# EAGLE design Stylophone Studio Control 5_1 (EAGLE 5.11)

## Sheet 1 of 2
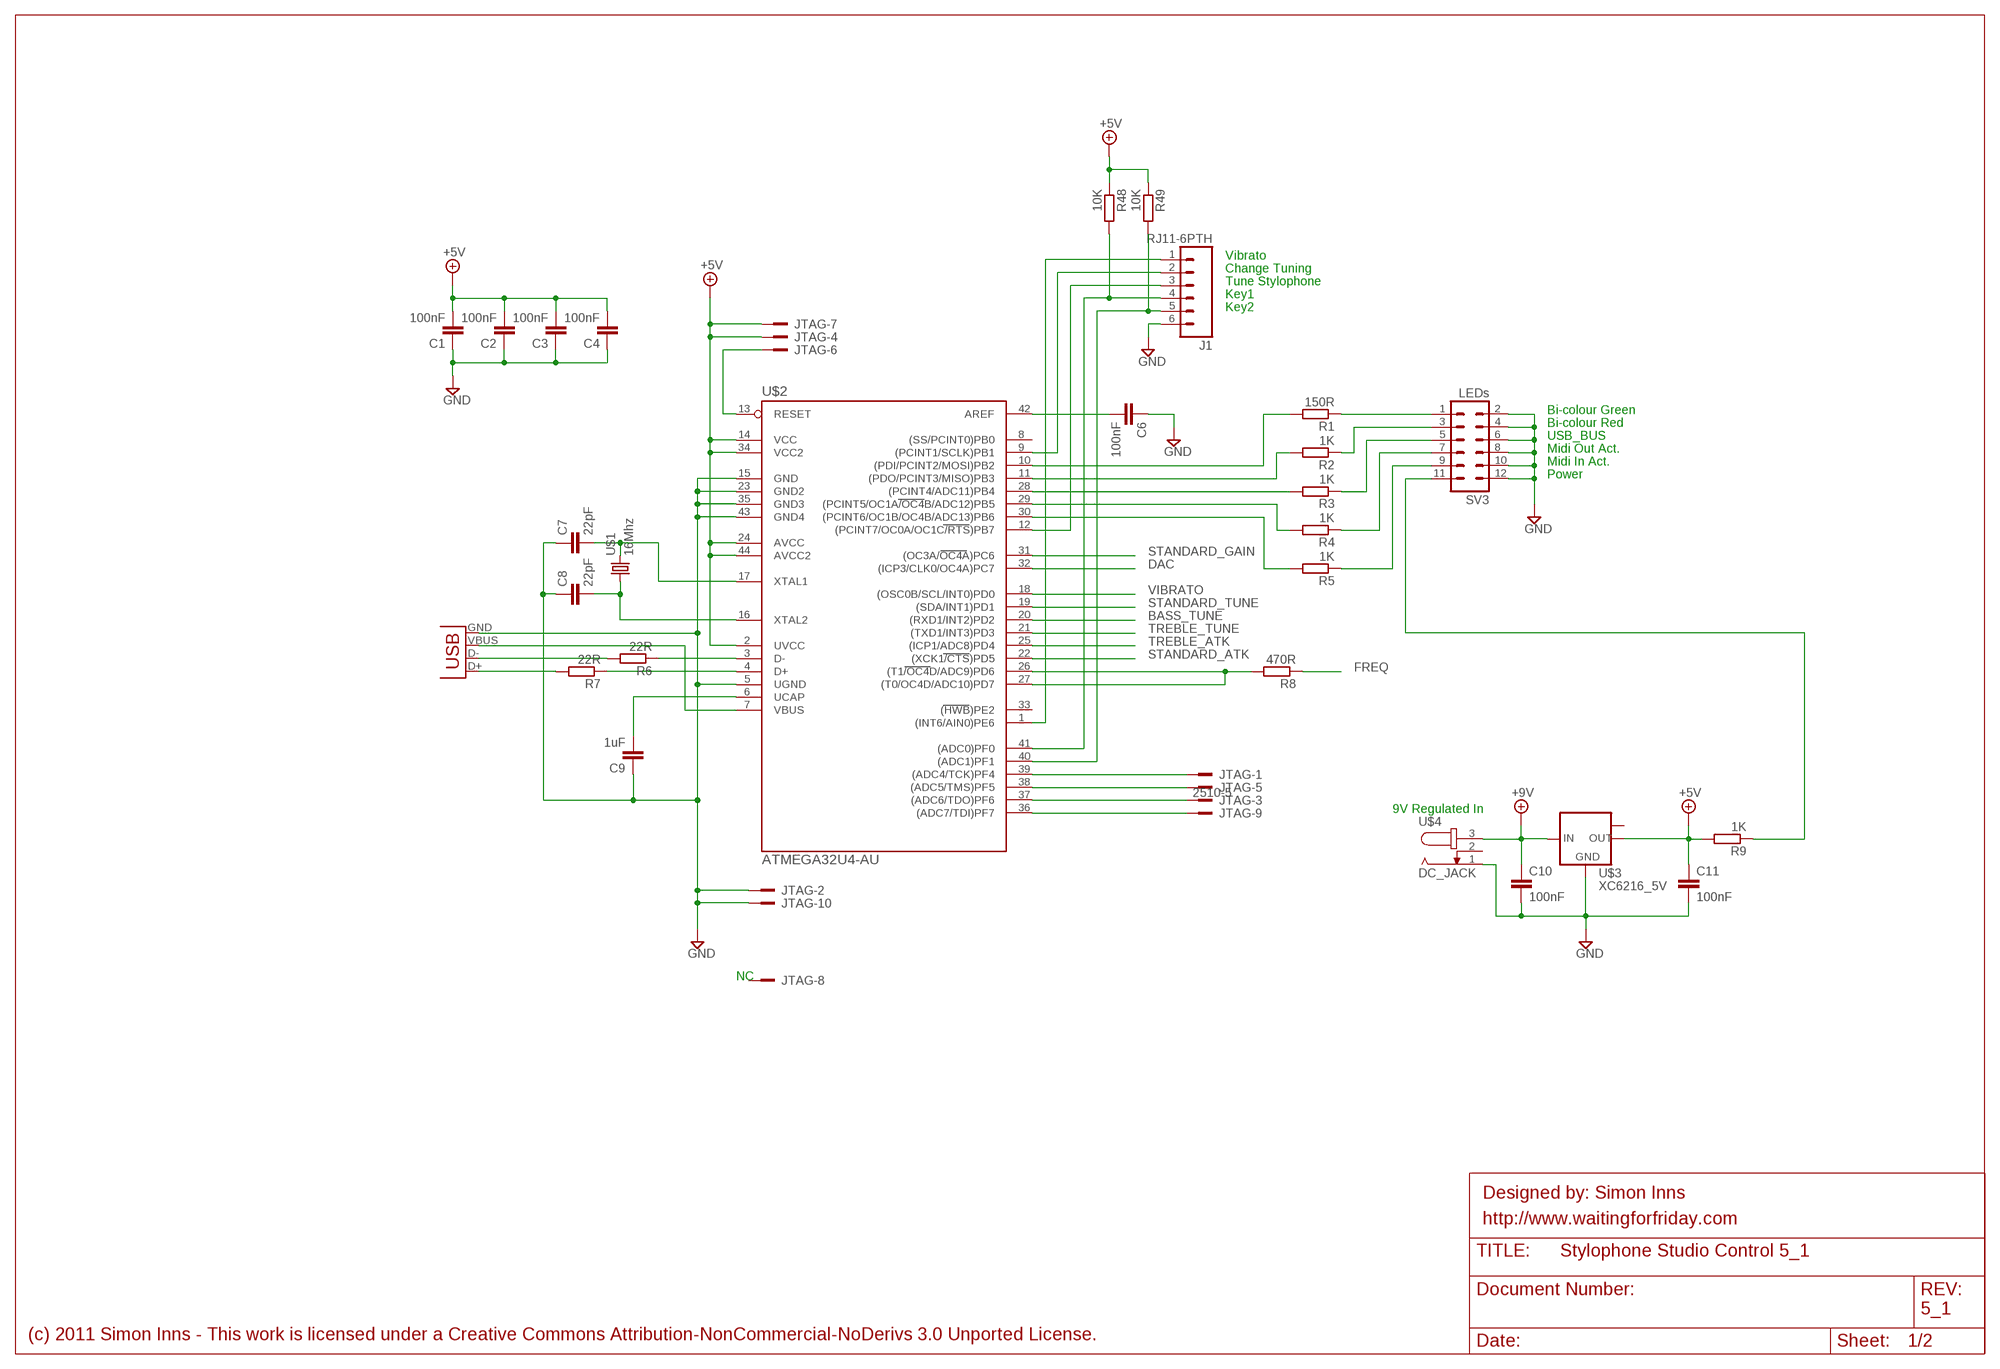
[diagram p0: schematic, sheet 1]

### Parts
C1  100nF  C-EUC0805K  [C0805K]
C2  100nF  C-EUC0805K  [C0805K]
C3  100nF  C-EUC0805K  [C0805K]
C4  100nF  C-EUC0805K  [C0805K]
C6  100nF  C-EUC0805K  [C0805K]
C7  22pF  C-EUC0805  [C0805]
C8  22pF  C-EUC0805  [C0805]
C9  1uF  C-EUC0805  [C0805]
C10  100nF  C-EUC0805K  [C0805K]
C11  100nF  C-EUC0805K  [C0805K]
J1  RJ11-6PTH  [RJ11-6]
JTAG  2510-5  [PAK100/2500-5-10]
R1  150R  R-EU_M1206  [M1206]
R2  1K  R-EU_M1206  [M1206]
R3  1K  R-EU_M1206  [M1206]
R4  1K  R-EU_M1206  [M1206]
R5  1K  R-EU_M1206  [M1206]
R6  22R  R-EU_M1206  [M1206]
R7  22R  R-EU_M1206  [M1206]
R8  470R  R-EU_M1206  [M1206]
R9  1K  R-EU_M1206  [M1206]
R48  10K  R-EU_M1206  [M1206]
R49  10K  R-EU_M1206  [M1206]
SV3  LEDs  MA06-2  [MA06-2]
U$1  16Mhz  CRYSTAL_SMD3X5MM  [CRYSTAL_SMD_3X5MM]
U$2  ATMEGA32U4-AU  [TQFP44]
U$3  XC6216_5V  [SOT223]
U$4  DC_JACK  [DC_JACK]
X1  USBPTH  [USB-B-PTH]

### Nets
+5V: C1.2 C2.2 C3.2 C4.2 C11.1 JTAG.4 JTAG.7 R9.2 R48.1 R49.1 U$2.2(UVCC) U$2.14(VCC) U$2.24(AVCC) U$2.34(VCC2) U$2.44(AVCC2) U$3.1(OUT) ; also sheet 2
+9V: C10.1 U$3.3(IN) U$4.3 ; also sheet 2
BASS_TUNE: U$2.20((RXD1/INT2)PD2) ; also sheet 2
DAC: U$2.32((ICP3/CLK0/OC4A)PC7) ; also sheet 2
FREQ: R8.1 ; also sheet 2
GND: C1.1 C2.1 C3.1 C4.1 C6.1 C7.1 C8.1 C9.1 C10.2 C11.2 J1.6 JTAG.2 JTAG.10 SV3.2 SV3.4 SV3.6 SV3.8 SV3.10 SV3.12 U$2.5(UGND) U$2.15(GND) U$2.23(GND2) U$2.35(GND3) U$2.43(GND4) U$3.2(GND) U$4.1 X1.GND ; also sheet 2
KEY1: J1.4 R48.2 U$2.41((ADC0)PF0)
KEY2: J1.5 R49.2 U$2.40((ADC1)PF1)
N$1: R8.2 U$2.26((T1/OC4D/ADC9)PD6) U$2.27((T0/OC4D/ADC10)PD7)
N$3: JTAG.6 U$2.13(RESET)
N$5: R9.1 SV3.11
N$6: R7.1 U$2.4(D+)
N$8: C8.2 U$1.1 U$2.16(XTAL2)
N$9: C7.2 U$1.2 U$2.17(XTAL1)
N$10: R3.2 U$2.28((PCINT4/ADC11)PB4)
N$12: R6.1 U$2.3(D-)
N$13: R7.2 X1.D+
N$14: R6.2 X1.D-
N$15: R4.2 U$2.29((PCINT5/OC1A/OC4B/ADC12)PB5)
N$19: U$2.7(VBUS) X1.VBUS
N$20: C9.2 U$2.6(UCAP)
N$31: R1.2 U$2.10((PDI/PCINT2/MOSI)PB2)
N$32: J1.1 U$2.1((INT6/AIN0)PE6)
N$33: R5.2 U$2.30((PCINT6/OC1B/OC4B/ADC13)PB6)
N$34: R2.2 U$2.11((PDO/PCINT3/MISO)PB3)
N$35: R1.1 SV3.1
N$36: R2.1 SV3.3
N$37: R3.1 SV3.5
N$38: R4.1 SV3.7
N$39: R5.1 SV3.9
N$41: J1.2 U$2.9((PCINT1/SCLK)PB1)
N$42: J1.3 U$2.12((PCINT7/OC0A/OC1C/RTS)PB7)
N$53: C6.2 U$2.42(AREF)
N$54: JTAG.1 U$2.39((ADC4/TCK)PF4)
N$55: JTAG.5 U$2.38((ADC5/TMS)PF5)
N$56: JTAG.3 U$2.37((ADC6/TDO)PF6)
N$57: JTAG.9 U$2.36((ADC7/TDI)PF7)
STANDARD_ATK: U$2.22((XCK1/CTS)PD5) ; also sheet 2
STANDARD_GAIN: U$2.31((OC3A/OC4A)PC6) ; also sheet 2
STANDARD_TUNE: U$2.19((SDA/INT1)PD1) ; also sheet 2
TREBLE_ATK: U$2.25((ICP1/ADC8)PD4) ; also sheet 2
TREBLE_TUNE: U$2.21((TXD1/INT3)PD3) ; also sheet 2
VIBRATO: U$2.18((OSC0B/SCL/INT0)PD0) ; also sheet 2
Unconnected: JTAG.8 U$2.8((SS/PCINT0)PB0) U$2.33((HWB)PE2) U$3.TAB(OUT1) U$4.2

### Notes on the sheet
- Vibrato
- Change Tuning
- Tune Stylophone
- Key1
- Key2
- Bi-colour Green
- Bi-colour Red
- USB_BUS
- Midi Out Act.
- Midi In Act.
- Power
- 9V Regulated In
- NC
- Designed by: Simon Inns
- http://www.waitingforfriday.com
- 5_1
- (c) 2011 Simon Inns - This work is licensed under a Creative Commons Attribution-NonCommercial-NoDerivs 3.0 Unported License.

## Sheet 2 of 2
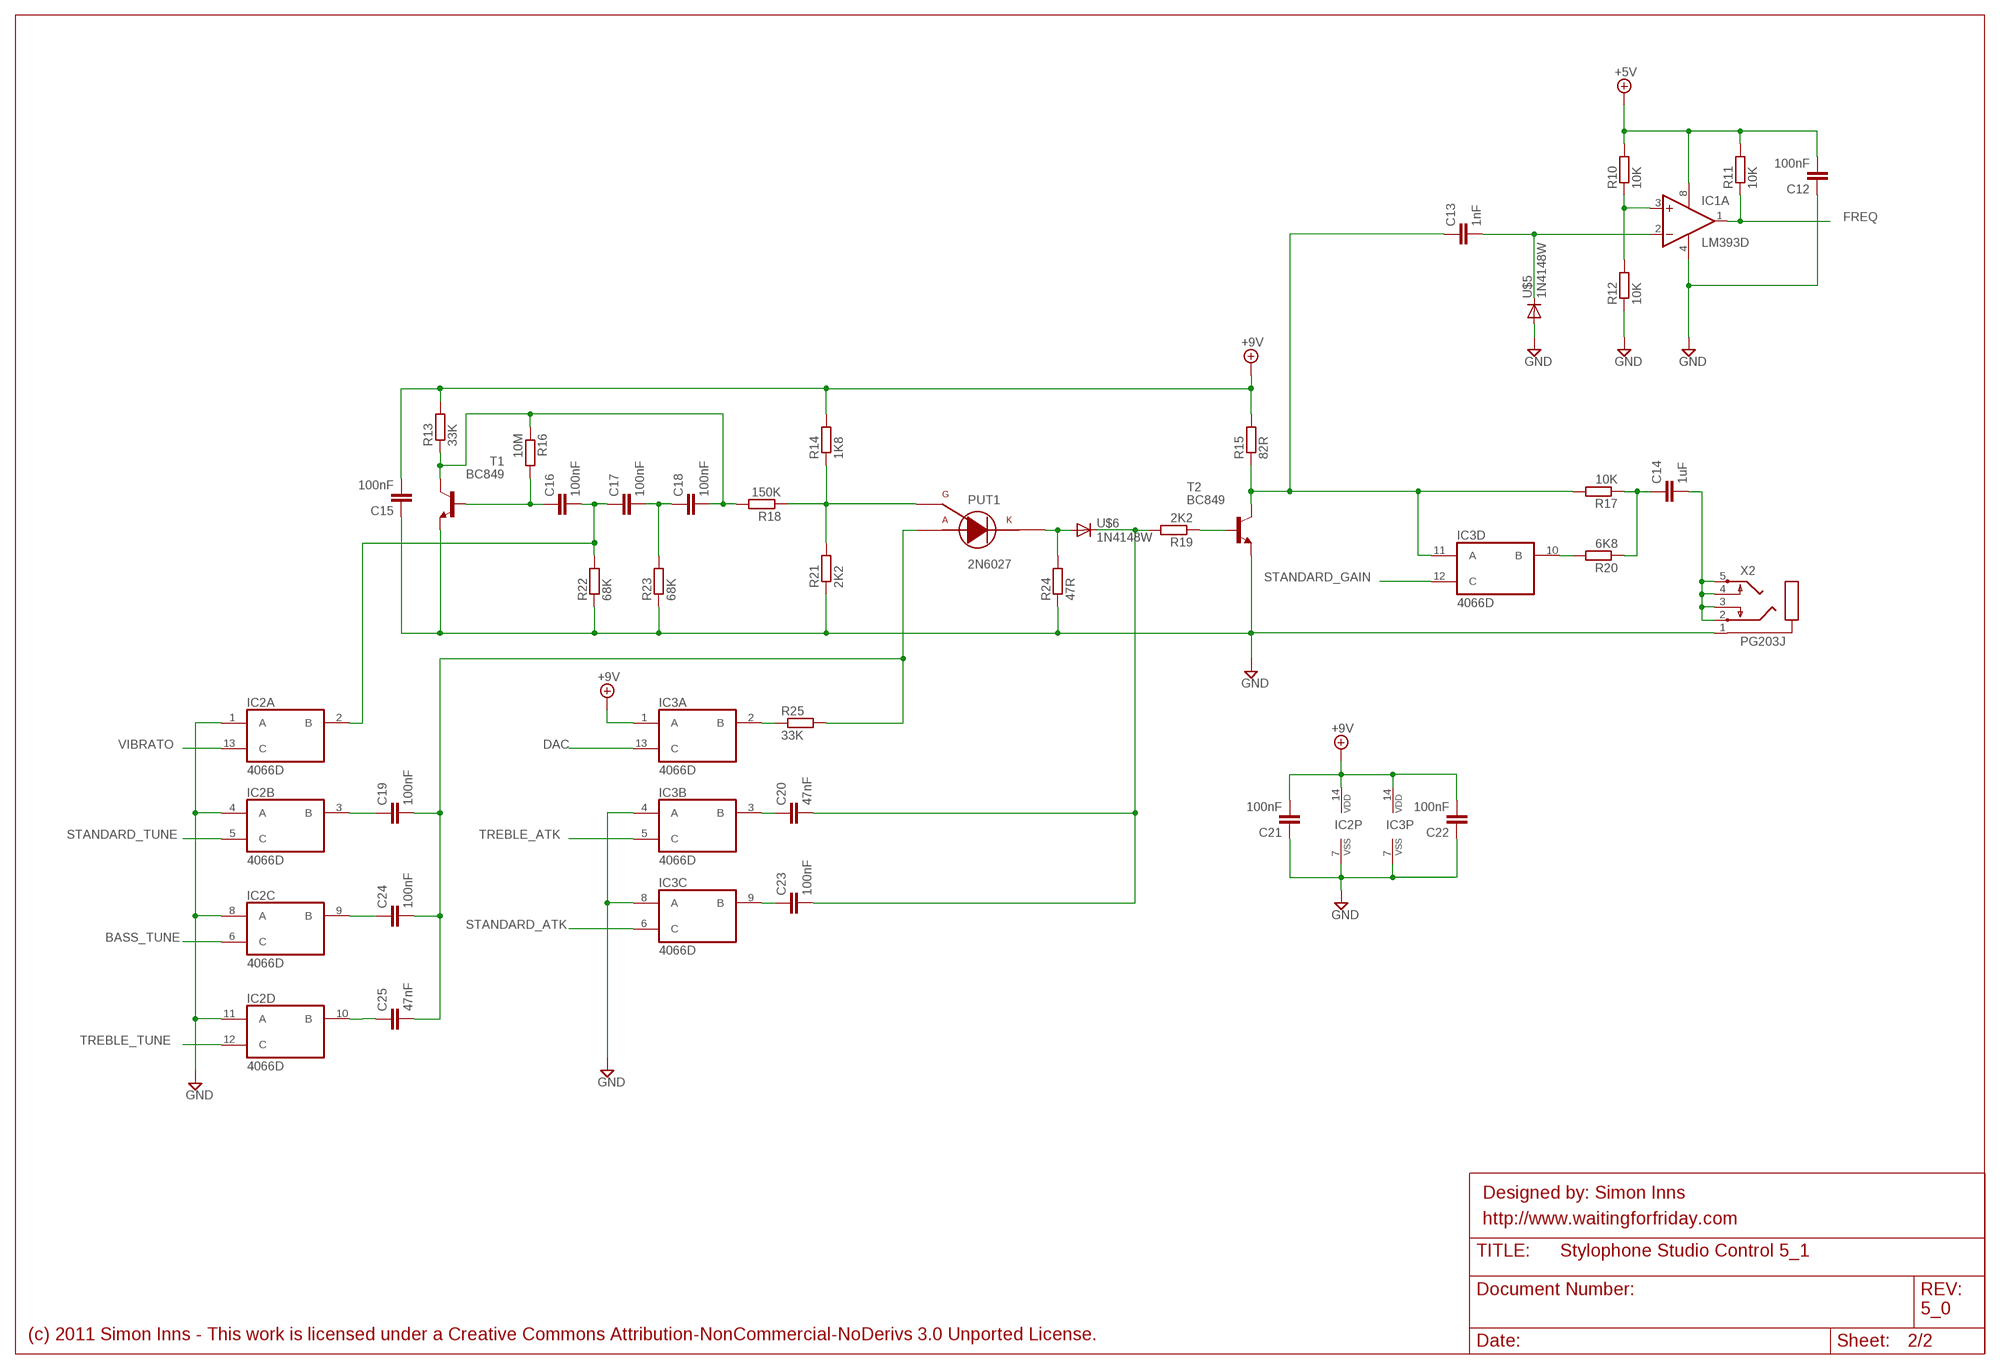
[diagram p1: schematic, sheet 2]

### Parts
C12  100nF  C-EUC0805K  [C0805K]
C13  1nF  C-EUC0805K  [C0805K]
C14  1uF  C-EUC0805K  [C0805K]
C15  100nF  C-EUC0805K  [C0805K]
C16  100nF  C-EUC0805K  [C0805K]
C17  100nF  C-EUC0805K  [C0805K]
C18  100nF  C-EUC0805K  [C0805K]
C19  100nF  C-EUC0805K  [C0805K]
C20  47nF  C-EUC0805K  [C0805K]
C21  100nF  C-EUC0805K  [C0805K]
C22  100nF  C-EUC0805K  [C0805K]
C23  100nF  C-EUC0805K  [C0805K]
C24  100nF  C-EUC0805K  [C0805K]
C25  47nF  C-EUC0805K  [C0805K]
IC1  LM393D  [SO08]
IC2  4066D  [SO14]
IC3  4066D  [SO14]
PUT1  2N6027  [TO-92]
R10  10K  R-EU_M1206  [M1206]
R11  10K  R-EU_M1206  [M1206]
R12  10K  R-EU_M1206  [M1206]
R13  33K  R-EU_M1206  [M1206]
R14  1K8  R-EU_M1206  [M1206]
R15  82R  R-EU_M1206  [M1206]
R16  10M  R-EU_M1206  [M1206]
R17  10K  R-EU_M1206  [M1206]
R18  150K  R-EU_M1206  [M1206]
R19  2K2  R-EU_M1206  [M1206]
R20  6K8  R-EU_M1206  [M1206]
R21  2K2  R-EU_M1206  [M1206]
R22  68K  R-EU_M1206  [M1206]
R23  68K  R-EU_M1206  [M1206]
R24  47R  R-EU_M1206  [M1206]
R25  33K  R-EU_M1206  [M1206]
T1  BC849  [SOT23]
T2  BC849  [SOT23]
U$5  1N4148W  [SOD123]
U$6  1N4148W  [SOD123]
X2  PG203J  [PG203J]

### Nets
+5V: C12.2 IC1.8(P:V+) R10.2 R11.2 ; also sheet 1
+9V: C15.2 C21.2 C22.2 IC2.14(P:VDD) IC3.1(A:A) IC3.14(P:VDD) R13.2 R14.2 R15.2 ; also sheet 1
BASS_TUNE: IC2.6(C:C) ; also sheet 1
CMP_V+1: C13.1 IC3.11(D:A) R15.1 R17.2 T2.3(C)
DAC: IC3.13(A:C) ; also sheet 1
FREQ: IC1.1(A:OUT) R11.1 ; also sheet 1
GND: C12.1 C15.1 C21.1 C22.1 IC1.4(P:V-) IC2.1(A:A) IC2.4(B:A) IC2.7(P:VSS) IC2.8(C:A) IC2.11(D:A) IC3.4(B:A) IC3.7(P:VSS) IC3.8(C:A) R12.1 R21.1 R22.1 R23.1 R24.1 T1.2(E) T2.2(E) U$5.A X2.1 ; also sheet 1
N$2: C13.2 IC1.2(A:-IN) U$5.C
N$4: IC1.3(A:+IN) R10.1 R12.2
N$7: C14.1 R17.1 R20.1
N$16: IC3.10(D:B) R20.2
N$58: C17.2 C18.1 R23.2
N$60: C18.2 R13.1 R16.1 R18.2 T1.3(C)
N$61: C16.1 R16.2 T1.1(B)
N$62: R19.1 T2.1(B)
N$63: PUT1.3(CATHODE) R24.2 U$6.A
N$64: C19.1 IC2.3(B:B)
N$65: C24.1 IC2.9(C:B)
N$66: C25.1 IC2.10(D:B)
N$67: PUT1.2(GATE) R14.1 R18.1 R21.2
N$68: C20.2 C23.2 R19.2 U$6.C
N$69: C14.2 X2.2 X2.3 X2.4 X2.5
N$70: IC3.2(A:B) R25.1
N$71: C19.2 C24.2 C25.2 PUT1.1(ANODE) R25.2
N$72: C16.2 C17.1 IC2.2(A:B) R22.2
N$73: C20.1 IC3.3(B:B)
N$74: C23.1 IC3.9(C:B)
STANDARD_ATK: IC3.6(C:C) ; also sheet 1
STANDARD_GAIN: IC3.12(D:C) ; also sheet 1
STANDARD_TUNE: IC2.5(B:C) ; also sheet 1
TREBLE_ATK: IC3.5(B:C) ; also sheet 1
TREBLE_TUNE: IC2.12(D:C) ; also sheet 1
VIBRATO: IC2.13(A:C) ; also sheet 1
Unconnected: IC1.5(B:+IN) IC1.6(B:-IN) IC1.7(B:OUT)

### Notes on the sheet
- Designed by: Simon Inns
- http://www.waitingforfriday.com
- 5_0
- (c) 2011 Simon Inns - This work is licensed under a Creative Commons Attribution-NonCommercial-NoDerivs 3.0 Unported License.

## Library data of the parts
C1-C4 C6-C25 = rcl:C-EU: CAPACITOR, European symbol
IC1 = linear:LM393: COMPARATOR
IC2 IC3 = 40xx:4066: Quad bilateral ANALOG SWITCH
J1 = SparkFun:RJ11-6: RJ11 Jack Simple 6 pin RJ11 jack. Commonly found on CAT3 devices and Microchip programmers. SKU: PRT-00132
JTAG = con-3m:2510-: 3M (TM) Pak 100 4-Wall Header Source: 3M; OC_FARNELL: 1788669; OC_NEWARK: unknown
PUT1 = simonslbr:2N6027: 2N6027 Programmable Unijunction Transistor in TO-92 packaging
R1-R25 R48 R49 = rcl:R-EU_: RESISTOR, European symbol
SV3 = con-lstb:MA06-2: PIN HEADER; OC_FARNELL: unknown; OC_NEWARK: unknown
T1 T2 = transistor:BC849: NPN TRANSISTOR
U$1 = simonslbr:CRYSTAL_SMD3X5MM: SMD Crystal 3.2mm X 5mm dual pads
U$2 = mega32U4:ATMEGA32U4-AU
U$3 = simonslbr:XC6216_5V: XC6216 LDO 5V Regulator
U$4 = simonslbr:DC_JACK: DC Jack with wider pads for easier soldering
U$5 U$6 = simonslbr:1N4148W: 1N4148W SOD-123 Surface mount diode
X1 = SparkFun:USB: USB Connectors USB-B-PTH is fully proven SKU : PRT-00139 USB-miniB is fully proven SKU : PRT-00587 USB-A-PCB is untested. USB-A-H is throughly reviewed, but untested. Spark Fun Electronics SKU : PRT-00437 USB-B-SMT is throughly reviewed, but untested. Needs silkscreen touching up. USB-A-S has not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
X2 = con-hirschmann:PG203J: MIC/HEADPHONE JACK KS-S stereo microphone/headphone jack PG203JN (Schukat); OC_FARNELL: unknown; OC_NEWARK: unknown

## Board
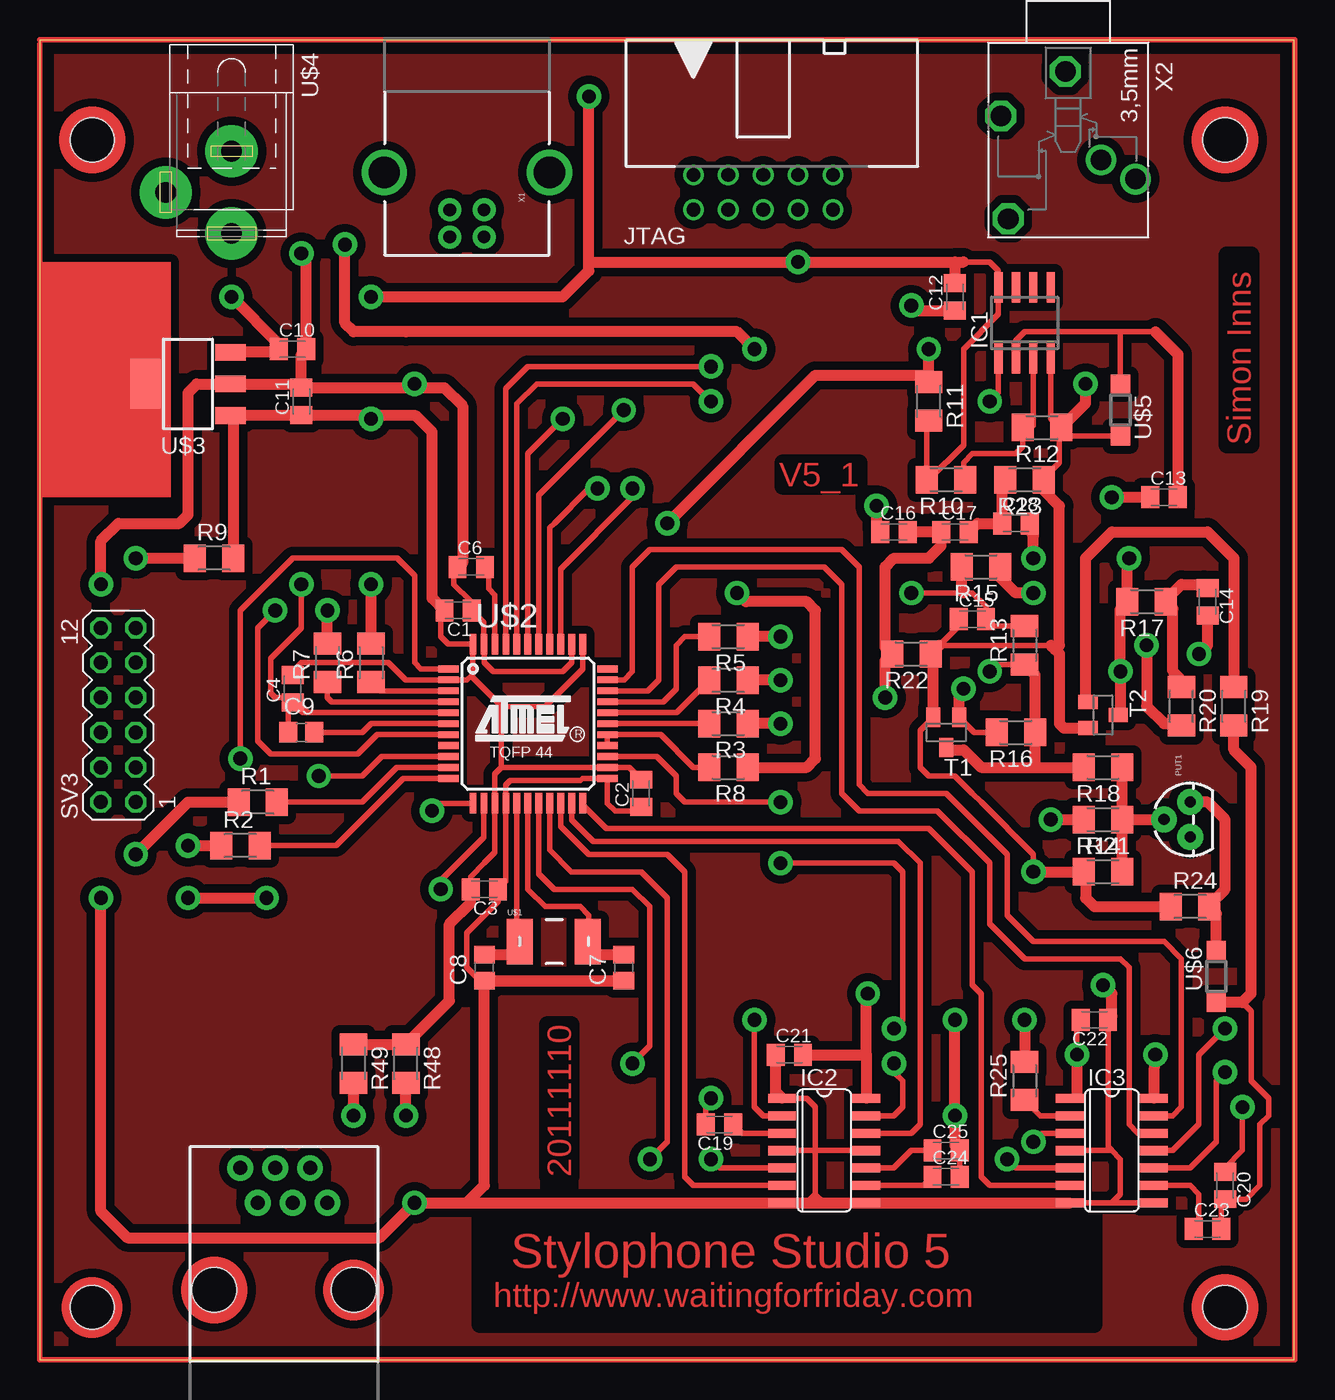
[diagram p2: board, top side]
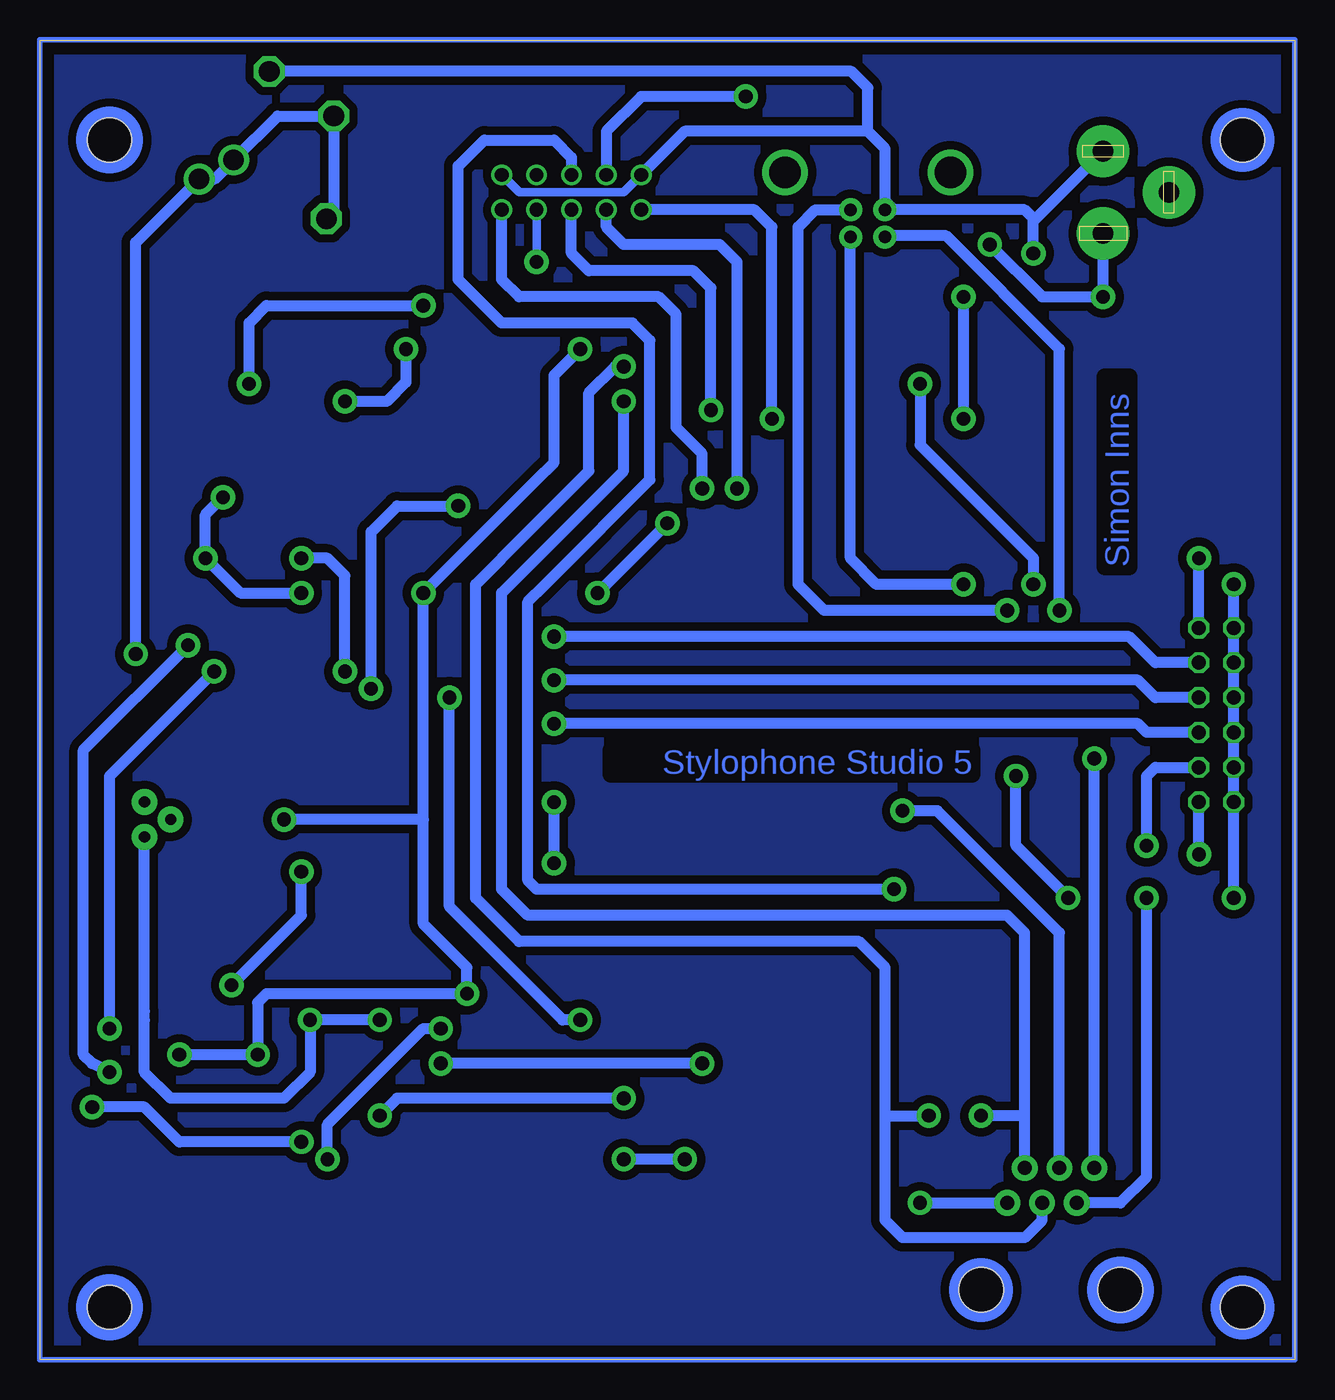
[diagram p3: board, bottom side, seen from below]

Size 91.42 x 96.19 mm. Coordinates in mm from the lower left corner, seen from the top.
Outline: 0,0 91.42,0 91.42,96.19 0,96.19 0,0
Copper layers (1*16): Top 0.035mm / dielectric 1.5mm / Bottom 0.035mm
Design rules "default": minimum track width 10mil, minimum drill 24mil, track to track 8mil, track to pad 8mil, pad to pad 8mil, via to via 8mil, smd to smd 8mil, copper to edge 40mil, drill to drill 8mil, minimum pad ring 10mil, minimum via ring 8mil, stop-mask expansion 4mil, vias tented up to drill 0mil, thermal gap 10mil
Holes 3.2 mm at 3.81,88.9 86.36,88.9 86.36,3.81 3.81,3.81
tRestrict: area 32.1,2.5 to 76.8,10.2

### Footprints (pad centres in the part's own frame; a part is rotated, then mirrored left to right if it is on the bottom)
C0805K = smd 1.3 x 1.6: 1 -1,0; 2 1,0
C0805 = smd 1.3 x 1.5: 1 -0.95,0; 2 0.95,0
SO08 = smd 0.6 x 2.2: 1 -1.905,-2.6; 2 -0.635,-2.6; 3 0.635,-2.6; 4 1.905,-2.6; 5 1.905,2.6; 6 0.635,2.6; 7 -0.635,2.6; 8 -1.905,2.6
SO14 = smd 0.66 x 2.032: 1 -3.81,-3.073; 2 -2.54,-3.073; 3 -1.27,-3.073; 4 0,-3.073; 5 1.27,-3.073; 6 2.54,-3.073; 7 3.81,-3.073; 8 3.81,3.073; 9 2.54,3.073; 10 1.27,3.073; 11 0,3.073; 12 -1.27,3.073; 13 -2.54,3.073; 14 -3.81,3.073
RJ11-6 = drill 1.016 pad 1.88 round: 1 1.905,8.89; 2 3.175,6.35; 3 4.445,8.89; 4 5.715,6.35; 5 6.985,8.89; 6 8.255,6.35 | hole 3.251: 0,0; 10.16,0
PAK100/2500-5-10 = drill 1 pad 1.422 round: 1 -5.08,-1.27; 2 -5.08,1.27; 3 -2.54,-1.27; 4 -2.54,1.27; 5 0,-1.27; 6 0,1.27; 7 2.54,-1.27; 8 2.54,1.27; 9 5.08,-1.27; 10 5.08,1.27
TO-92 = drill 0.813 pad 1.88 round: 1 -1.27,0; 2 0,1.905; 3 1.27,0
M1206 = smd 1.6 x 2: 1 -1.4,0; 2 1.4,0
MA06-2 = drill 1.016 octagon: 1 -6.35,-1.27; 2 -6.35,1.27; 3 -3.81,-1.27; 4 -3.81,1.27; 5 -1.27,-1.27; 6 -1.27,1.27; 7 1.27,-1.27; 8 1.27,1.27; 9 3.81,-1.27; 10 3.81,1.27; 11 6.35,-1.27; 12 6.35,1.27
SOT23 = smd 1 x 1.4: 1 -0.95,-1.1; 2 0.95,-1.1; 3 0,1.1
CRYSTAL_SMD_3X5MM = smd 1.9 x 3.302: 1 -2.485,-0.007; 2 2.468,-0.007
TQFP44 = smd 1.5 x 0.5: 1 -5.8,4; 2 -5.8,3.2; 3 -5.8,2.4; 4 -5.8,1.6; 5 -5.8,0.8; 6 -5.8,0; 7 -5.8,-0.8; 8 -5.8,-1.6; 9 -5.8,-2.4; 10 -5.8,-3.2; 11 -5.8,-4; 23 5.8,-4; 24 5.8,-3.2; 25 5.8,-2.4; 26 5.8,-1.6; 27 5.8,-0.8; 28 5.8,0; 29 5.8,0.8; 30 5.8,1.6; 31 5.8,2.4; 32 5.8,3.2; 33 5.8,4 | smd 0.5 x 1.5: 12 -4,-5.8; 13 -3.2,-5.8; 14 -2.4,-5.8; 15 -1.6,-5.8; 16 -0.8,-5.8; 17 0,-5.8; 18 0.8,-5.8; 19 1.6,-5.8; 20 2.4,-5.8; 21 3.2,-5.8; 22 4,-5.8; 34 4,5.8; 35 3.2,5.8; 36 2.4,5.8; 37 1.6,5.8; 38 0.8,5.8; 39 0,5.8; 40 -0.8,5.8; 41 -1.6,5.8; 42 -2.4,5.8; 43 -3.2,5.8; 44 -4,5.8
SOT223 = smd 1.219 x 2.235: 1 -2.311,-3.099; 2 0,-3.099; 3 2.311,-3.099 | smd 3.6 x 2.2: TAB 0,3.099
DC_JACK = drill 1.5 pad 3.81 round: 1 -0.46,0; 2 2.54,-4.8; 3 5.54,0
SOD123 = smd 1.4 x 1.4: A 1.9,0; C -1.9,0
USB-B-PTH = drill 0.914 pad 1.676 round: D+ 0,1.25; D- 1.981,1.25; GND 0,-1.25; VBUS 1.981,-1.25 | drill 2.286 round: S1 -2.718,-6.02; S2 -2.718,6.02
PG203J = drill 1.499 octagon: 1 -5.004,-0.203; 4 5.74,-4.369; 5 -1.753,-4.902 | drill 1.499 round: 2 2.845,4.902; 3 1.448,2.388

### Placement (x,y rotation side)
C1  30.48,54.61 180 top
C2  43.81,41.27 90 top
C3  32.38,34.29 180 top
C4  18.41,48.9 90 top
C6  31.43,57.78 0 top
C7  42.55,28.57 90 top
C8  32.38,28.57 90 top
C9  19.05,45.72 0 top
C10  18.41,73.66 0 top
C11  19.05,69.85 90 top
C12  66.67,77.47 90 top
C13  81.92,62.87 0 top
C14  85.09,55.24 270 top
C15  67.94,53.98 0 top
C16  62.23,60.33 0 top
C17  66.67,60.33 0 top
C18  71.12,60.96 0 top
C19  49.53,17.14 180 top
C20  86.36,12.7 270 top
C21  54.61,22.23 0 top
C22  76.83,24.77 180 top
C23  85.09,9.53 0 top
C24  66.04,13.34 0 top
C25  66.04,15.24 0 top
IC1  71.75,75.56 0 top
IC2  57.15,15.24 270 top
IC3  78.11,15.24 270 top
J1  12.7,5.08 0 top
JTAG  52.7,85.09 0 top
PUT1  83.82,39.37 90 top
R1  15.88,40.64 0 top
R2  14.61,37.47 0 top
R3  50.16,46.35 180 top
R4  50.16,49.53 180 top
R5  50.16,52.7 180 top
R6  24.13,50.8 90 top
R7  20.95,50.8 90 top
R8  50.16,43.18 180 top
R9  12.7,58.42 0 top
R10  66.04,64.14 180 top
R11  64.77,69.85 270 top
R12  73.03,67.94 180 top
R13  71.75,52.07 90 top
R14  77.47,39.37 180 top
R15  68.58,57.78 180 top
R16  71.12,45.72 180 top
R17  80.64,55.24 180 top
R18  77.47,43.18 180 top
R19  87,47.62 270 top
R20  83.19,47.62 270 top
R21  77.47,35.56 0 top
R22  63.5,51.44 180 top
R23  71.75,64.14 180 top
R24  83.82,33.02 0 top
R25  71.75,20.32 90 top
R48  26.67,21.59 270 top
R49  22.86,21.59 270 top
SV3  5.71,46.99 90 top
T1  66.04,45.72 180 top
T2  77.47,46.99 270 top
U$1  37.47,30.48 0 top
U$2  35.56,46.35 0 top
U$3  10.79,71.12 90 top
U$4  13.97,87.63 270 top
U$5  78.74,69.22 270 top
U$6  85.72,27.94 90 top
X1  31.11,83.82 270 top
X2  74.93,88.9 270 top

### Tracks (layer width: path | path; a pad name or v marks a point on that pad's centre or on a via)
+5V  (via drill 1 pad 1.78)
  Top 0.406: C3.2 31.39,35.2 32.38,36.2 33.16,36.97 U$2.14 33.16,42.41 33.16,42.69 33.63,43.16 | C2.2 42.94,43.16 U$2.24 33.63,43.16 | C1.2 29.21,54.34 29.21,52.7 29.76,52.16 U$2.44 31.56,49.98 31.43,49.85 | 31.43,49.85 31.11,49.53 31.09,49.55 U$2.2 29.73,49.53 26.67,49.53 25.4,50.8 19.05,50.8 18.41,50.16 C4.2 | 33.63,43.16 33.63,47.65 | 33.63,47.65 31.43,49.85 | U$2.34 39.56,50.35 36.83,47.62 33.66,47.62 33.63,47.65 | R11.2 64.64,68.32 R10.2 64.77,64.14 67.31,66.67 67.31,73.66 69.85,76.2 IC1.8 69.85,79.38 69.22,80.01 67.31,80.01
  Top 0.61: 24.13,68.81 v24.13,68.58
  Top 0.813: 19.05,68.81 U$3.1 14.1,68.6 R9.2 | 19.05,68.81 C11.1 | 19.05,68.81 24.13,68.81 27.39,68.81 28.57,67.63 28.57,55.52 C1.2 | 40.01,80.01 40.01,79.38 38.1,77.47 25.4,77.47 24.77,77.47 v24.13,77.47 | 40.01,80.01 v40.01,92.08 | 40.01,80.01 v55.24,80.01 66.67,80.01 | R49.1 R48.1 29.84,26.16 29.84,31.75 31.39,33.29 C3.2 | 66.67,80.01 67.31,80.01 | 66.67,80.01 C12.2
  Bottom 0.61: v55.24,80.01 JTAG.7
  Bottom 0.813: JTAG.4 50.16,89.53 47.62,92.08 v40.01,92.08 | v24.13,68.58 v24.13,77.47
+9V  (via drill 1 pad 1.78)
  Top 0.406: 75.56,19.15 IC3.1 | C22.2 75.56,24.5 v75.56,22.23 | R13.2 69.45,53.47 C15.2 68.94,54.88 67.94,55.88 67.31,55.88 v63.5,55.88
  Top 0.813: U$3.3 17.19,73.43 C10.1 17.41,74.03 v13.97,77.47 | IC3.14 81.18,21.06 v81.28,22.23 | v75.56,22.23 75.56,19.15 | 60.22,22.23 IC2.14 | 60.22,22.23 60.22,26.57 v60.33,26.67 | v52.07,73.66 50.8,74.93 26.67,74.93 22.86,74.93 22.23,75.56 v22.23,81.28 | C21.2 60.22,22.23 | v73.66,39.37 R14.2 | R15.2 67.18,56.01 67.31,55.88
  Bottom 0.813: U$4.3 v13.97,77.47 18.41,77.47 v22.23,81.28 | v81.28,22.23 v75.56,22.23 75.56,26.04 74.93,26.67 v60.33,26.67 60.33,28.57 63.5,31.75 63.5,39.37 | 63.5,39.37 v63.5,55.88 56.52,62.87 55.24,64.14 53.98,65.41 53.98,71.75 v52.07,73.66 | 63.5,39.37 v73.66,39.37
BASS_TUNE
  Top 0.406: U$2.20 37.96,38.88 40.01,36.83 45.72,36.83 46.99,35.56 46.99,13.34 47.62,12.7 IC2.6
CMP_V+1  (via drill 1 pad 1.78)
  Top 0.406: IC3.11 81.92,15.24 82.55,15.24 83.19,15.88 84.45,17.14 84.45,18.41 84.45,22.23 v86.36,24.13
  Top 0.813: T2.3 78.74,47.16 v78.74,50.16 78.74,54.74 R17.2 79.25,58.29 v79.38,58.42 | v78.11,62.87 C13.1 | R15.1 69.98,57.02 71.12,55.88 v72.39,55.88
  Bottom 0.813: v86.36,24.13 86.36,42.55 v78.74,50.16 | v78.11,62.87 79.38,61.59 v79.38,58.42 76.83,55.88 v72.39,55.88
DAC
  Top 0.406: U$2.32 42.57,49.55 43.18,50.16 43.18,57.78 44.45,59.05 58.42,59.05 59.69,57.78 59.69,41.91 60.33,41.27 66.04,41.27 70.48,36.83 70.48,32.38 72.39,30.48 81.92,30.48 83.19,29.21 83.19,18.41 82.55,17.78 IC3.13
FREQ  (via drill 1 pad 1.78)
  Top 0.406: IC1.1 69.85,70.48 v69.22,69.85
  Top 0.813: 64.77,71.75 R11.1 | 64.77,71.75 v64.77,73.66 | R8.1 55.88,43.18 56.52,43.81 56.52,54.61 55.88,55.24 51.44,55.24 v50.8,55.88 | v45.72,60.96 56.52,71.75 64.77,71.75
  Bottom 0.813: v69.22,69.85 66.17,69.85 R11.1 v64.77,73.66 | v50.8,55.88 v45.72,60.96
GND  (via drill 1 pad 1.78)
  Top 0.406: C2.1 43.55,40.01 41.91,40.01 41.36,40.55 U$2.23 39.56,42.35 39.37,42.23 34.29,42.23 33.96,41.9 U$2.15 33.96,34.87 C3.1 33.38,33.38 31.11,31.11 31.11,28.57 31.75,27.94 32.07,27.94 C8.1 | U$2.35 38.76,50.83 38.1,50.16 33.02,50.16 32.38,50.8 32.38,52.13 U$2.43 32.36,53.73 C1.1 31.39,54.7 31.39,55.29 30.16,56.52 30.16,57.52 C6.1 | 17.78,46.04 C9.1 18.1,47.58 C4.1 19.16,47.16 U$2.5 19.52,47.16 18.41,48.26 17.14,48.26 16.83,48.58 16.83,51.12 19.05,53.34 v19.05,56.52 | 55.88,11.43 IC2.7 55.88,11.43 | IC2.8 57.15,11.43 56.52,12.06 | 55.88,11.43 56.52,12.06 | 56.52,12.06 56.52,15.24 | 56.52,15.24 56.52,18.41 55.88,19.05 IC2.1 | 56.52,15.24 IC2.4 | 56.52,15.24 IC2.11 | IC3.8 IC3.7 78.11,11.43 78.74,12.06 78.74,14.61 78.11,15.24 | 78.11,15.24 IC3.4 78.11,15.24 | 56.52,15.24 IC2.11 | 56.52,12.06 56.52,15.24 | 55.88,11.43 56.52,12.06 | 56.52,15.24 IC2.11 | 56.52,12.06 56.52,15.24 | 78.11,15.24 77.83,15.51 C22.1 | 65.53,52.07 73.66,52.07 | v72.39,35.56 72.39,36.83 68.58,40.64 67.94,41.27 66.67,42.55 64.77,42.55 64.14,43.18 64.14,45.87 T1.2 | C15.1 66.94,53.48 R22.1 | R23.1 73.16,64.27 74.3,65.41 74.3,67.18 R12.1 | R12.1 74.42,67.81 73.66,68.58 IC1.4 | U$5.A 74.43,67.31 R12.1
  Top 0.813: C11.2 19.05,71.12 U$3.2 11.43,71.12 10.79,70.48 10.79,61.59 10.16,60.96 5.71,60.96 4.45,59.69 v4.45,56.52 | C11.2 19.05,73.3 C10.2 19.41,80.28 v19.05,80.64 | C11.2 27.3,70.85 | 27.3,70.85 29.48,70.85 30.8,69.53 30.8,58.05 C6.1 | v4.45,33.66 4.45,10.79 6.35,8.89 24.77,8.89 v27.3,11.43 31.11,11.43 | 27.3,70.85 v27.3,71.12 | C8.1 C7.1 32.7,27.62 32.38,27.3 32.38,12.7 31.11,11.43 | 31.11,11.43 55.88,11.43 57.15,11.43 IC3.7 | IC2.1 53.61,19.52 C21.1 | R21.1 v72.39,35.56 R21.1 | v77.47,27.3 78.11,26.67 78.11,25.04 C22.1 | R24.1 76.83,33.02 76.2,33.66 76.2,35.43 R21.1 | T2.2 74.61,46.04 74.3,46.35 74.3,51.44 73.98,51.75 | 73.66,52.07 73.98,51.75 | 65.53,52.07 R22.1 65.09,51.24 T1.2 | R23.1 73.16,63.37 74.3,62.23 74.3,52.07 73.98,51.75 | C12.1 63.87,76.47 v63.5,76.83 | v76.2,71.12 76.2,69.72 R12.1
  Bottom 0.61: JTAG.2 48.9,85.09 56.52,85.09 JTAG.10
  Bottom 0.813: v19.05,80.64 19.05,83.01 18.96,83.1 | 18.96,83.1 U$4.1 | 29.21,83.82 19.68,83.82 18.96,83.1 | 29.21,83.82 X1.GND | SV3.6 SV3.4 SV3.2 v4.45,33.66 | SV3.6 SV3.8 SV3.10 SV3.12 | SV3.6 v4.45,56.52 | JTAG.2 44.45,89.53 31.11,89.53 | 30.8,89.22 29.84,88.27 29.84,84.45 29.21,83.82 | 30.8,89.22 31.11,89.53 | X2.1 32.31,93.9 31.11,92.71 31.11,89.53 | 30.8,89.22 31.11,89.53 | v27.3,11.43 J1.6 | v19.05,56.52 19.05,58.42 27.3,66.67 v27.3,71.12 | v72.39,35.56 72.39,32.38 v77.47,27.3 | v63.5,76.83 74.93,76.83 76.2,75.56 v76.2,71.12
KEY1  (via drill 1 pad 1.78)
  Top 0.406: U$2.41 33.96,70.79 35.56,72.39 v48.9,72.39
  Top 0.813: v26.67,17.78 R48.2
  Bottom 0.813: v48.9,72.39 49.53,72.39 51.44,70.48 51.44,64.77 52.7,63.5 55.88,60.33 59.69,56.52 59.69,33.66 56.52,30.48 31.75,30.48 29.84,28.57 29.84,17.78 | 29.84,17.78 29.84,10.16 28.57,8.89 19.68,8.89 18.41,10.16 J1.4 | 29.84,17.78 v26.67,17.78
KEY2  (via drill 1 pad 1.78)
  Top 0.406: U$2.40 34.76,69.69 36.2,71.12 47.62,71.12 v48.9,69.85
  Top 0.813: v22.86,17.78 R49.2
  Bottom 0.813: v48.9,69.85 48.9,64.77 52.07,61.59 55.24,58.42 57.78,55.88 57.78,34.29 55.88,32.38 20.95,32.38 19.68,31.11 19.68,17.78 | J1.5 19.68,17.78 | 19.68,17.78 v22.86,17.78
N$1
  Top 0.406: U$2.26 U$2.27 45.25,45.55 47.62,43.18 R8.2
N$2
  Top 0.406: 78.74,74.93 71.75,74.93 71.12,74.3 IC1.2 | 78.74,74.93 81.28,74.93 | 78.74,74.93 U$5.C
  Top 0.813: C13.2 82.92,73.3 81.28,74.93
N$3  (via drill 1 pad 1.78)
  Top 0.406: v29.21,34.29 29.21,34.92 31.75,37.47 32.36,38.08 U$2.13
  Bottom 0.813: JTAG.6 52.7,87.63 53.98,88.9 59.05,88.9 60.96,87 60.96,78.74 57.78,75.56 48.26,75.56 46.99,74.3 46.99,64.14 53.98,57.15 54.61,56.52 55.88,55.24 55.88,34.92 55.24,34.29 v29.21,34.29
N$4
  Top 0.406: R10.1 67.31,64.27 67.31,65.41 67.94,66.04 71.12,66.04 71.62,66.55 R12.2 | R12.2 71.75,67.31 | IC1.3 72.39,68.08 R12.2
  Top 0.813: R10.1 67.31,64.27
N$5  (via drill 1 pad 1.78)
  Top 0.813: v6.99,58.42 R9.1
  Bottom 0.813: SV3.11 v6.99,58.42
N$6
  Top 0.406: U$2.4 21.26,47.95 20.95,48.26 R7.1
N$7
  Top 0.813: C14.1 84.82,56.52 83.19,56.52 82.05,55.38 R17.1 82.55,54.74 82.55,50.16 83.19,49.53 R20.1
N$8
  Top 0.406: U$2.16 34.76,30.69 U$1.1 34.04,29.53
  Top 0.813: C8.2 34.6,29.52 34.92,29.84 34.92,30.42 U$1.1
N$9
  Top 0.406: U$2.17 35.56,34.29 36.83,33.02 39.37,33.02 40.01,32.38 40.01,30.55 U$1.2
  Top 0.813: C7.2 40.32,29.52 40.01,29.21 40.01,30.4 U$1.2
N$10
  Top 0.406: U$2.28 R3.2
N$11
  pour Top (isolate 0.61): 0,95.89 91.44,95.89 91.44,0 0,0
N$12
  Top 0.406: U$2.3 24.77,48.76 R6.1
N$13  (via drill 1 pad 1.78)
  Top 0.813: R7.2 v20.95,54.61
  Bottom 0.813: v20.95,54.61 34.29,54.61 36.2,56.52 36.2,82.55 34.92,83.82 X1.D+
N$14  (via drill 1 pad 1.78)
  Top 0.813: R6.2 v24.13,56.52
  Bottom 0.813: v24.13,56.52 30.48,56.52 32.38,58.42 32.38,81.82 X1.D-
N$15
  Top 0.406: U$2.29 46.39,47.16 R4.2
N$16  (via drill 1 pad 1.78)
  Top 0.406: IC3.10 83.82,13.97 85.72,15.88 85.72,20.32 v86.36,20.95
  Top 0.813: v80.64,52.07 80.64,47.62 81.92,46.35 83.06,46.35 R20.2
  Bottom 0.813: v86.36,20.95 87.63,21.59 88.27,22.23 88.27,44.45 v80.64,52.07
N$17
  pour Bottom (isolate 0.61): 0,95.89 91.44,95.89 91.44,0 0,0
N$18
  Top 0.406: 0,96.2 91.44,96.2 91.44,0 0,0 0,95.89
N$19  (via drill 1 pad 1.78)
  Top 0.406: U$2.7 24.6,45.55 23.18,44.13 16.83,44.13 15.88,45.09 15.88,53.34 v17.14,54.61
  Bottom 0.813: v17.14,54.61 17.14,73.66 25.4,81.92 29.79,81.92 X1.VBUS
N$20
  Top 0.406: U$2.6 24.13,46.35 23.5,45.72 C9.2
N$21
  Bottom 0.406: 0,96.2 91.44,96.2 91.44,0 0,0 0,96.2
N$31
  Top 0.406: U$2.10 26.01,43.16 23.5,40.64 R1.2
N$32  (via drill 1 pad 1.78)
  Top 0.406: U$2.1 27.75,50.35 27.3,50.8 27.3,57.15 26.04,58.42 18.41,58.42 14.61,54.61 v14.61,43.81
  Bottom 0.813: J1.1 v14.61,43.81
N$33
  Top 0.406: U$2.30 45.28,47.95 45.41,47.95 46.35,48.9 46.35,52.07 46.99,52.7 R5.2
N$34
  Top 0.406: U$2.11 26.48,42.35 21.59,37.47 R2.2
N$35  (via drill 1 pad 1.78)
  Top 0.813: R1.1 10.79,40.64 v6.99,36.83
  Bottom 0.813: v6.99,36.83 SV3.1
N$36  (via drill 1 pad 1.78)
  Top 0.813: v10.79,37.47 R2.1
  Bottom 0.813: v10.79,37.47 10.79,42.55 10.16,43.18 SV3.3
N$37  (via drill 1 pad 1.78)
  Top 0.813: v53.98,46.35 R3.1
  Bottom 0.813: v53.98,46.35 11.43,46.35 10.79,45.72 SV3.5
N$38  (via drill 1 pad 1.78)
  Top 0.813: v53.98,49.53 R4.1
  Bottom 0.813: v53.98,49.53 11.43,49.53 10.16,48.26 SV3.7
N$39  (via drill 1 pad 1.78)
  Top 0.813: v53.98,52.7 R5.1
  Bottom 0.813: v53.98,52.7 12.06,52.7 10.16,50.8 SV3.9
N$41  (via drill 1 pad 1.78)
  Top 0.406: U$2.9 24.91,43.95 23.5,42.55 v20.32,42.55
  Top 0.813: v10.79,33.66 v16.51,33.66
  Bottom 0.813: v20.32,42.55 20.32,37.47 v16.51,33.66 | v10.79,33.66 10.79,13.34 12.7,11.43 J1.2
N$42  (via drill 1 pad 1.78)
  Top 0.406: v28.57,40.01 29.12,40.55 U$2.12
  Bottom 0.813: J1.3 17.14,31.11 26.04,40.01 v28.57,40.01
N$53
  Top 0.406: U$2.42 33.16,55.74 32.7,56.2 32.7,57.52 C6.2
N$54  (via drill 1 pad 1.78)
  Top 0.406: U$2.39 35.56,66.04 v38.1,68.58
  Bottom 0.813: v38.1,68.58 38.1,82.55 39.37,83.82 JTAG.1
N$55  (via drill 1 pad 1.78)
  Top 0.406: U$2.38 36.36,63.03 v42.55,69.22
  Bottom 0.813: v42.55,69.22 42.55,78.11 43.81,79.38 51.44,79.38 52.7,80.64 JTAG.5
N$56  (via drill 1 pad 1.78)
  Top 0.406: v40.64,63.5 40.01,63.5 37.47,60.96 37.16,60.66 U$2.37
  Bottom 0.813: JTAG.3 50.16,82.55 48.9,81.28 41.91,81.28 40.64,80.01 v40.64,63.5
N$57  (via drill 1 pad 1.78)
  Top 0.406: U$2.36 37.96,57.65 43.18,62.87 v43.18,63.5
  Bottom 0.813: v43.18,63.5 43.18,66.04 45.09,67.94 45.09,76.2 46.35,77.47 56.52,77.47 57.78,78.74 JTAG.9
N$58
  Top 0.813: R23.2 70.12,63.9 C18.1 68.31,60.96 C17.2
N$60  (via drill 1 pad 1.78)
  Top 0.406: R13.1 69.72,50.67 v69.22,50.16
  Top 0.813: 72.39,43.18 R18.2 | R13.1 72.52,49.91 R16.1 72.52,43.31 72.39,43.18 | 72.39,43.18 68.58,43.18 67.31,44.45 66.21,44.45 T1.3 | v72.39,58.42 72.39,60.05 C18.2
  Bottom 0.813: v72.39,58.42 70.48,58.42 69.22,57.15 v69.22,50.16
N$61  (via drill 1 pad 1.78)
  Top 0.406: R16.2 68.09,45.72 T1.1
  Top 0.813: T1.1 66.99,48.58 v67.31,48.9 | v60.96,62.23 60.96,60.59 C16.1
  Bottom 0.813: v67.31,48.9 67.31,60.33 65.41,62.23 v60.96,62.23
N$62
  Top 0.813: R19.1 87,58.42 85.09,60.33 78.11,60.33 76.2,58.42 76.2,48.11 T2.1
N$63
  Top 0.813: PUT1.3 85.09,40.64 86.36,39.37 86.36,34.29 85.22,33.15 R24.2 85.72,32.52 U$6.A
N$64
  Top 0.406: IC2.3 51.16,16.51 C19.1
N$65
  Top 0.406: IC2.9 64.41,12.7 C24.1
N$66
  Top 0.406: IC2.10 62.23,13.97 63.5,15.24 C25.1
N$67
  Top 0.813: R21.2 R14.1 | R14.1 PUT1.2 | R14.1 R18.1
N$68
  Top 0.406: C23.2 86.09,11.43 C20.2 87.9,11.7 88.9,12.7 88.9,17.14 89.53,17.78 89.53,19.05 88.27,20.32 88.27,25.4 87.62,26.04
  Top 0.813: U$6.C 87.62,26.04 88.27,26.68 88.27,43.18 87,44.45 R19.2
N$69  (via drill 1 pad 1.78)
  Top 0.813: C14.2 85.09,52.07 v84.45,51.44
  Bottom 0.813: X2.4 70.03,83.69 X2.5 74.12,90.65 X2.3 78.72,86.06 X2.2 84.45,81.43 v84.45,51.44
N$70
  Top 0.406: IC3.2 72.89,17.78 R25.1
N$71  (via drill 1 pad 1.78)
  Top 0.406: C25.2 C24.2 | C19.2 48.53,18.78 v48.9,19.05
  Top 0.813: C25.2 66.67,15.61 v66.67,17.78 v66.67,24.77 | v71.75,24.77 R25.2
  Bottom 0.813: v48.9,19.05 65.41,19.05 v66.67,17.78 | v66.67,24.77 v71.75,24.77 71.75,20.95 73.66,19.05 81.92,19.05 83.82,20.95 83.82,24.77 83.82,25.4 PUT1.1
N$72  (via drill 1 pad 1.78)
  Top 0.406: IC2.2 52.7,17.78 52.07,18.41 v52.07,24.77
  Top 0.813: v61.59,48.26 61.59,50.93 R22.2 61.59,51.94 61.59,57.78 62.23,58.42 64.77,58.42 65.67,59.33 C17.1 C16.2
  Bottom 0.813: v52.07,24.77 53.34,24.77 61.59,33.02 v61.59,48.26
N$73  (via drill 1 pad 1.78)
  Top 0.406: v72.39,15.88 73.03,16.51 IC3.3 | C20.1 86.36,13.97 87.63,15.24 v87.63,18.41
  Bottom 0.813: v87.63,18.41 83.82,18.41 81.28,15.88 v72.39,15.88
N$74
  Top 0.406: IC3.9 83.82,12.7 84.45,12.06 84.45,9.89 C23.1
STANDARD_ATK
  Top 0.406: U$2.22 39.56,40.45 41.27,38.73 64.77,38.73 67.94,35.56 67.94,27.3 68.58,26.67 68.58,13.34 69.22,12.7 IC3.6
STANDARD_GAIN
  Top 0.406: U$2.31 44.31,48.76 45.09,49.53 45.09,56.52 46.35,57.78 57.15,57.78 58.42,56.52 58.42,41.27 59.69,40.01 65.41,40.01 69.22,36.2 69.22,31.75 71.75,29.21 78.74,29.21 79.38,28.57 79.38,17.14 80.01,16.51 IC3.12
STANDARD_TUNE  (via drill 1 pad 1.78)
  Top 0.406: U$2.19 37.16,37.13 38.73,35.56 43.81,35.56 45.72,33.66 45.72,15.88 v44.45,14.61 | v48.9,14.61 49.53,13.97 IC2.5
  Bottom 0.813: v44.45,14.61 v48.9,14.61
TREBLE_ATK  (via drill 1 pad 1.78)
  Top 0.406: U$2.25 44.95,43.95 46.35,42.55 46.35,41.27 46.99,40.64 v53.98,40.64 | v53.98,36.2 62.23,36.2 62.87,35.56 62.87,24.77 v62.23,24.13 | v70.48,14.61 71.12,13.97 IC3.5
  Bottom 0.813: v53.98,36.2 v53.98,40.64 | v62.23,24.13 63.5,24.13 70.48,17.14 v70.48,14.61
TREBLE_TUNE
  Top 0.406: U$2.21 38.76,39.34 40.32,37.78 46.04,37.78 46.67,37.78 62.55,37.78 64.14,36.2 64.14,17.14 63.5,16.51 IC2.12
VIBRATO  (via drill 1 pad 1.78)
  Top 0.406: U$2.18 36.36,35.4 37.47,34.29 43.18,34.29 44.45,33.02 44.45,22.86 v43.18,21.59 | v62.23,21.59 62.23,20.95 62.87,20.32 62.87,18.41 62.23,17.78 IC2.13
  Bottom 0.813: v43.18,21.59 v62.23,21.59
(copper drawn outside any net)
  shapes: Bottom circle x6, Top area x1, Top circle x6

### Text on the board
Top: Simon Inns | V5_1 | 20111110 | Stylophone Studio 5 | http://www.waitingforfriday.com
Bottom: Simon Inns | Stylophone Studio 5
